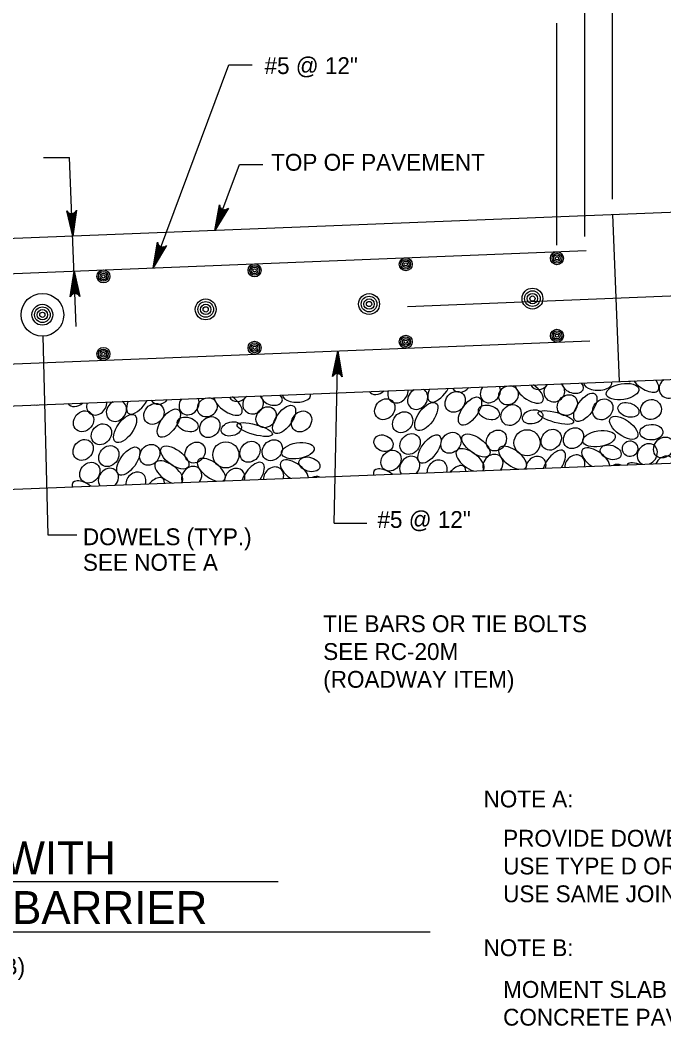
# Model space of a CAD drawing. Extents: x 638167 to 640248, y 296544 to 298920.
# Drawn here: x 638445.2 to 638562.8, y 297453.3 to 297636.8 of the extents above; entities that cross this region are included whole.
import ezdxf

# ---------------------------------------------------------------- set-up
doc = ezdxf.new("R2010")
doc.units = 0
doc.layers.add('1', color=7, linetype='Continuous')
doc.layers.add('50', color=7, linetype='Continuous')

# ---------------------------------------------------------------- blocks, each defined once
blk = doc.blocks.new('BAR')
at = {"layer": '50'}
for radius in [2, 1.5, 1, 0.5]:
    blk.add_circle((0, 0), radius, dxfattribs=at)

msp = doc.modelspace()

# ---------------------------------------------------------------- linework, layer by layer
at = {"layer": '1'}
for p, q in [((638553.41, 297604.17), (638553.41, 297675.98)), ((638548.33, 297597.34), (638548.33, 297644.05)), ((638543.25, 297595.78), (638543.25, 297636.27)), ((638469.52, 297591.61), (638483.33, 297628.66)), ((638483.33, 297628.66), (638487.58, 297628.66)), ((638449.48, 297611.78), (638454.25, 297611.78)), ((638455.48, 297580.89), (638454.25, 297611.78)), ((638480.8, 297598.42), (638485.3, 297610.49)), ((638485.3, 297610.49), (638489.55, 297610.49)), ((638604.24, 297603.35), (638311.35, 297591.64)), ((638553.41, 297601.32), (638554.63, 297570.86)), ((638422.08, 297589.71), (638548.59, 297594.77)), ((638515.95, 297584.57), (638592.09, 297587.62)), ((638449.38, 297579.15), (638450.28, 297542.91)), ((638380.16, 297571.51), (638549.25, 297578.28)), ((638502.56, 297545), (638503.22, 297576.43)), ((638318.5, 297561.42), (638605.46, 297572.9)), ((638384.24, 297548.8), (638606.06, 297557.67)), ((638502.56, 297545), (638508.51, 297545)), ((638450.28, 297542.91), (638455.57, 297542.91)), ((638332.08, 297479.61), (638492.33, 297479.61)), ((638303.87, 297470.46), (638520.07, 297470.46))]:
    msp.add_line(p, q, dxfattribs=at)
for points in [[(638480.8, 297598.42), (638481.62, 297603.13), (638481.67, 297602.91), (638481.72, 297602.7), (638481.84, 297602.56), (638481.95, 297602.41), (638482.09, 297602.33), (638482.23, 297602.25), (638482.39, 297602.22), (638482.55, 297602.19), (638482.73, 297602.23), (638482.91, 297602.26), (638483.09, 297602.38), (638483.27, 297602.51), (638480.8, 297598.42), (638483.09, 297602.38), (638482.91, 297602.26), (638480.8, 297598.42), (638482.73, 297602.23), (638482.55, 297602.19), (638480.8, 297598.42), (638482.39, 297602.22), (638482.23, 297602.25), (638480.8, 297598.42), (638482.09, 297602.33), (638481.95, 297602.41), (638480.8, 297598.42), (638481.84, 297602.56), (638481.72, 297602.7), (638480.8, 297598.42), (638481.67, 297602.91)], [(638454.83, 297597.38), (638453.76, 297602.04), (638453.89, 297601.86), (638454.02, 297601.68), (638454.18, 297601.6), (638454.34, 297601.51), (638454.5, 297601.49), (638454.66, 297601.47), (638454.82, 297601.5), (638454.97, 297601.54), (638455.13, 297601.63), (638455.28, 297601.73), (638455.4, 297601.92), (638455.52, 297602.11), (638454.83, 297597.38), (638455.4, 297601.92), (638455.28, 297601.73), (638454.83, 297597.38), (638455.13, 297601.63), (638454.97, 297601.54), (638454.83, 297597.38), (638454.82, 297601.5), (638454.66, 297601.47), (638454.83, 297597.38), (638454.5, 297601.49), (638454.34, 297601.51), (638454.83, 297597.38), (638454.18, 297601.6), (638454.02, 297601.68), (638454.83, 297597.38), (638453.89, 297601.86)], [(638469.52, 297591.61), (638470.33, 297596.32), (638470.39, 297596.11), (638470.44, 297595.89), (638470.56, 297595.75), (638470.67, 297595.61), (638470.81, 297595.53), (638470.95, 297595.45), (638471.1, 297595.42), (638471.26, 297595.39), (638471.44, 297595.42), (638471.62, 297595.45), (638471.8, 297595.58), (638471.98, 297595.7), (638469.52, 297591.61), (638471.8, 297595.58), (638471.62, 297595.45), (638469.52, 297591.61), (638471.44, 297595.42), (638471.26, 297595.39), (638469.52, 297591.61), (638471.1, 297595.42), (638470.95, 297595.45), (638469.52, 297591.61), (638470.81, 297595.53), (638470.67, 297595.61), (638469.52, 297591.61), (638470.56, 297595.75), (638470.44, 297595.89), (638469.52, 297591.61), (638470.39, 297596.11)], [(638455.08, 297591.03), (638456.15, 297586.37), (638456.01, 297586.55), (638455.88, 297586.73), (638455.72, 297586.81), (638455.56, 297586.9), (638455.4, 297586.92), (638455.24, 297586.94), (638455.09, 297586.91), (638454.93, 297586.87), (638454.78, 297586.77), (638454.62, 297586.67), (638454.5, 297586.49), (638454.39, 297586.3), (638455.08, 297591.03), (638454.5, 297586.49), (638454.62, 297586.67), (638455.08, 297591.03), (638454.78, 297586.77), (638454.93, 297586.87), (638455.08, 297591.03), (638455.09, 297586.91), (638455.24, 297586.94), (638455.08, 297591.03), (638455.4, 297586.92), (638455.56, 297586.9), (638455.08, 297591.03), (638455.72, 297586.81), (638455.88, 297586.73), (638455.08, 297591.03), (638456.01, 297586.55)], [(638503.22, 297576.43), (638504, 297571.72), (638503.88, 297571.9), (638503.76, 297572.09), (638503.6, 297572.18), (638503.44, 297572.28), (638503.29, 297572.31), (638503.13, 297572.34), (638502.97, 297572.32), (638502.81, 297572.29), (638502.66, 297572.2), (638502.5, 297572.11), (638502.37, 297571.93), (638502.24, 297571.76), (638503.22, 297576.43), (638502.37, 297571.93), (638502.5, 297572.11), (638503.22, 297576.43), (638502.66, 297572.2), (638502.81, 297572.29), (638503.22, 297576.43), (638502.97, 297572.32), (638503.13, 297572.34), (638503.22, 297576.43), (638503.29, 297572.31), (638503.44, 297572.28), (638503.22, 297576.43), (638503.6, 297572.18), (638503.76, 297572.09), (638503.22, 297576.43), (638503.88, 297571.9)]]:
    msp.add_lwpolyline(points, dxfattribs=at)
for centre, radius in [((638449.29, 297583.05), 3.9), ((638537.79, 297559.68), 2.39), ((638482.79, 297557.48), 2.39)]:
    msp.add_circle(centre, radius, dxfattribs=at)
for centre, major_axis, ratio, start_param, end_param in [((638531.09, 297568.9), (1.29, 1.57), 0.844245, 1.646659, 5.92418), ((638534.4, 297568.36), (-1.73, -0.77), 0.87402, 4.347672, 10.501851), ((638538.21, 297569.02), (-2.44, 1.76), 0.479042, 0.443803, 4.744324), ((638540.14, 297571.33), (1.29, 1.57), 0.844245, 2.798262, 4.772577), ((638542.76, 297568.99), (-1.75, -0.78), 0.948581, 5.012713, 9.897231), ((638546.19, 297570.07), (1.88, -0.58), 0.646802, 3.301963, 7.121802), ((638550.71, 297570.58), (2.57, 0), 0.504072, 3.123827, 6.463685), ((638555.31, 297569.2), (1.29, 1.57), 0.844245, 6.27398, 6.458399), ((638559.29, 297571.03), (-2.44, 1.76), 0.479042, 1.014341, 4.173787), ((638563.78, 297569.66), (-1.75, -0.78), 0.948581, 4.858014, 10.05193), ((638483.21, 297566.82), (-2.44, 1.76), 0.479042, 0.443803, 4.744324), ((638485.13, 297569.13), (1.29, 1.57), 0.844245, 2.798262, 4.772577), ((638487.76, 297566.79), (-1.75, -0.78), 0.948581, 5.012713, 9.897231), ((638491.19, 297567.87), (1.88, -0.58), 0.646802, 3.301963, 7.121802), ((638495.71, 297568.38), (2.57, 0), 0.504072, 3.123827, 6.463685), ((638510.43, 297570.4), (1.29, 1.57), 0.844245, 2.967408, 4.603431), ((638514.21, 297568.86), (1.29, 1.57), 0.844245, 2.008108, 5.562731), ((638517.81, 297567.7), (1.29, 1.57), 0.844245, 1.11244, 6.458399), ((638521.76, 297569.7), (-1.76, -2.44), 0.479042, 5.130486, 8.155839), ((638525.79, 297570.83), (1.29, 1.57), 0.844245, 2.840874, 4.729965), ((638448.37, 297568.49), (1.29, 1.57), 0.844245, 3.627473, 3.943366), ((638455.42, 297568.2), (1.29, 1.57), 0.844245, 2.967408, 4.603431), ((638459.2, 297566.66), (1.29, 1.57), 0.844245, 2.008108, 5.562731), ((638462.81, 297565.5), (1.29, 1.57), 0.844245, 1.11244, 6.458399), ((638466.76, 297567.5), (-1.76, -2.44), 0.479042, 5.130486, 8.155839), ((638470.79, 297568.63), (1.29, 1.57), 0.844245, 2.840874, 4.729965), ((638476.09, 297566.7), (1.29, 1.57), 0.844245, 1.646659, 5.92418), ((638479.4, 297566.16), (-1.73, -0.77), 0.87402, 4.347672, 10.501851), ((638535.15, 297556.93), (-2.44, 1.76), 0.479042, 2.873239, 8.598074), ((638550.32, 297556.66), (-2.44, 1.76), 0.479042, 3.57213, 7.899183), ((638559.74, 297557.6), (1.29, 1.57), 0.844245, 4.147339, 9.706685), ((638516.35, 297555.32), (1.29, 1.57), 0.844245, 4.644979, 9.209045), ((638527.38, 297556.49), (-2.44, 1.76), 0.479042, 3.037298, 8.434015), ((638531.55, 297555.67), (1.29, 1.57), 0.844245, 4.815265, 9.038759), ((638539.41, 297555.3), (1.29, 1.57), 0.844245, 5.200099, 8.653925), ((638542.71, 297555.75), (-1.76, -2.44), 0.479042, 1.685696, 5.317444), ((638546.51, 297555.56), (1.29, 1.57), 0.844245, 5.210279, 8.643745), ((638562.99, 297555.35), (1.29, 1.57), 0.844245, 5.676034, 8.17799), ((638461.35, 297553.12), (1.29, 1.57), 0.844245, 4.644979, 9.209045), ((638472.38, 297554.29), (-2.44, 1.76), 0.479042, 3.037298, 8.434015), ((638476.55, 297553.47), (1.29, 1.57), 0.844245, 4.815265, 9.038759), ((638480.14, 297554.73), (-2.44, 1.76), 0.479042, 2.873239, 8.598074), ((638487.71, 297553.55), (-1.76, -2.44), 0.479042, 1.685696, 5.317444), ((638491.51, 297553.36), (1.29, 1.57), 0.844245, 5.210279, 8.643745), ((638495.31, 297554.46), (-2.44, 1.76), 0.479042, 3.57213, 7.899183), ((638521.36, 297554.62), (1.29, 1.57), 0.844245, 5.179508, 8.674516), ((638524.48, 297552.96), (-1.76, -2.44), 0.479042, 2.538262, 4.464878), ((638554.02, 297553.84), (1.29, 1.57), 0.844245, 0.243434, 1.04422), ((638559.74, 297553.94), (3.63, -1.8), 0.282192, 2.12602, 3.204967), ((638466.36, 297552.42), (1.29, 1.57), 0.844245, 5.179508, 8.674516), ((638469.48, 297550.76), (-1.76, -2.44), 0.479042, 2.538262, 4.464878), ((638484.41, 297553.1), (1.29, 1.57), 0.844245, 5.200099, 8.653925), ((638499.02, 297551.64), (1.29, 1.57), 0.844245, 0.243434, 1.04422), ((638512.29, 297552.82), (-2.44, 1.76), 0.479042, 4.69169, 6.779622), ((638457.29, 297550.62), (-2.44, 1.76), 0.479042, 4.69169, 6.779622)]:
    msp.add_ellipse(centre, major_axis=major_axis, ratio=ratio, start_param=start_param, end_param=end_param, dxfattribs=at)
for centre, major_axis, ratio in [((638555.23, 297569.03), (-2.97, -0.48), 0.479042), ((638524.66, 297567.16), (1.29, 1.57), 0.844245), ((638527.37, 297565.48), (-1.76, -2.44), 0.479042), ((638545.14, 297566.55), (1.29, 1.57), 0.844245), ((638548.43, 297566.16), (-1.76, -2.44), 0.479042), ((638469.66, 297564.96), (1.29, 1.57), 0.844245), ((638472.37, 297563.28), (-1.76, -2.44), 0.479042), ((638490.14, 297564.35), (1.29, 1.57), 0.844245), ((638493.42, 297563.96), (-1.76, -2.44), 0.479042), ((638511.81, 297565.81), (1.29, 1.57), 0.844245), ((638519.39, 297564.49), (-1.76, -2.44), 0.479042), ((638530.82, 297565.23), (1.88, -0.58), 0.646802), ((638534.87, 297564.75), (1.29, 1.57), 0.844245), ((638551.61, 297565.78), (1.29, 1.57), 0.844245), ((638556.29, 297565.69), (1.88, -0.58), 0.646802), ((638560.43, 297565.76), (-1.75, -0.78), 0.948581), ((638456.81, 297563.61), (1.29, 1.57), 0.844245), ((638464.39, 297562.29), (-1.76, -2.44), 0.479042), ((638475.82, 297563.03), (1.88, -0.58), 0.646802), ((638479.87, 297562.55), (1.29, 1.57), 0.844245), ((638496.61, 297563.58), (1.29, 1.57), 0.844245), ((638515.07, 297563.44), (1.29, 1.57), 0.844245), ((638538.8, 297564.42), (1.84, 0.44), 0.666084), ((638543.06, 297564.3), (3.23, -0.89), 0.276285), ((638555.44, 297562.43), (-2.44, 1.76), 0.479042), ((638460.07, 297561.24), (1.29, 1.57), 0.844245), ((638483.8, 297562.22), (1.84, 0.44), 0.666084), ((638488.06, 297562.1), (3.23, -0.89), 0.276285), ((638546.27, 297560.53), (1.29, 1.57), 0.844245), ((638560.49, 297561.62), (2.11, 0.08), 0.671766), ((638511.58, 297559.61), (1.64, -0.76), 0.796199), ((638516.43, 297559.46), (1.29, 1.57), 0.844245), ((638519.98, 297558.55), (-1.76, -2.44), 0.479042), ((638523.9, 297559.69), (1.29, 1.57), 0.844245), ((638528.46, 297559.19), (-2.44, 1.76), 0.479042), ((638532.18, 297560.1), (1.29, 1.57), 0.844245), ((638542.2, 297560.25), (1.29, 1.57), 0.844245), ((638550.93, 297560.43), (-2.97, -0.48), 0.479042), ((638562.73, 297558.83), (1.29, 1.57), 0.844245), ((638456.74, 297558.38), (1.29, 1.57), 0.844245), ((638461.43, 297557.26), (1.29, 1.57), 0.844245), ((638464.98, 297556.35), (-1.76, -2.44), 0.479042), ((638468.9, 297557.49), (1.29, 1.57), 0.844245), ((638473.46, 297556.99), (-2.44, 1.76), 0.479042), ((638477.18, 297557.9), (1.29, 1.57), 0.844245), ((638487.2, 297558.05), (1.29, 1.57), 0.844245), ((638491.27, 297558.33), (1.29, 1.57), 0.844245), ((638495.93, 297558.23), (-2.97, -0.48), 0.479042), ((638553.06, 297557.95), (1.88, -0.58), 0.646802), ((638556.6, 297558.61), (-0.06, 1.43), 0.982495), ((638498.05, 297555.75), (1.88, -0.58), 0.646802), ((638512.95, 297556.43), (1.29, 1.57), 0.844245), ((638457.95, 297554.23), (1.29, 1.57), 0.844245)]:
    msp.add_ellipse(centre, major_axis=major_axis, ratio=ratio, dxfattribs=at)

# ---------------------------------------------------------------- block references
at = {"layer": '1', "xscale": 0.5953136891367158, "yscale": 0.5953136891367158, "rotation": -82.05765865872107}
for p in [(638543.25, 297593.37), (638488.03, 297591.16), (638515.64, 297592.26), (638460.43, 297590.05), (638515.64, 297578.12), (638543.25, 297579.23), (638460.43, 297575.91), (638488.03, 297577.02)]:
    msp.add_blockref('BAR', p, dxfattribs=at)
at = {"layer": '1', "xscale": 0.9524673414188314, "yscale": 0.9524673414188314}
for p in [(638508.94, 297585.01), (638538.77, 297586), (638449.29, 297583.05), (638479.11, 297584.03)]:
    msp.add_blockref('BAR', p, dxfattribs=at)

# ---------------------------------------------------------------- texts
at = {"layer": '1'}
for s, height, p in [('#5 @ 12"', 3.072, (638489.85, 297626.98)), ('TOP OF PAVEMENT', 3.072, (638491.06, 297609.34)), ('NOTE A:', 3.072, (638529.84, 297493.15)), ('PROVIDE DOWELS AT EXPANSION JOINTS.', 3.072, (638533.42, 297485.98)), ('MOMENT SLAB (AT-GRADE) WITH', 6, (638332.53, 297480.94)), ('USE TYPE D OR E JOINT PER RC-20M.', 3.072, (638533.42, 297480.91)), ('USE SAME JOINT AS PROVIDED IN PAVEMENT.', 3.072, (638533.42, 297475.84)), ('PRECAST 42" F-SHAPE CONCRETE BARRIER', 6, (638305.37, 297471.87)), ('NOTE B:', 3.072, (638529.84, 297466)), ('(SEE SHEET 6 FOR PLAN OF C.I.P. MOMENT SLAB)', 3.072, (638345.94, 297462.58)), ('MOMENT SLAB DEPTH TO MATCH DEPTH OF', 3.072, (638533.42, 297458.39)), ('CONCRETE PAVEMENT IN ROADWAY.', 3.072, (638533.42, 297453.32))]:
    msp.add_text(s, height=height, dxfattribs=at).set_placement(p)
for s, p in [('#5 @ 12"', (638510.47, 297544.15)), ('DOWELS (TYP.)', (638456.69, 297541)), ('SEE NOTE A', (638456.69, 297536.33)), ('TIE BARS OR TIE BOLTS', (638500.57, 297525.13)), ('SEE RC-20M', (638500.57, 297520.05)), ('(ROADWAY ITEM)', (638500.57, 297514.98))]:
    msp.add_text(s, height=3.072, rotation=360, dxfattribs=at).set_placement(p)

doc.saveas('drawing.dxf')
